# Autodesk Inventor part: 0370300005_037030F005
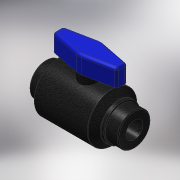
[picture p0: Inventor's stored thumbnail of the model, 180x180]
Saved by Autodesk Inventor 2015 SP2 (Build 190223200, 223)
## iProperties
Created: 2017-06
Part Number: 0370300005_037030F005
Material: PVC-Piping
Description: PLASSON BALL VALVE DN20 FEMALE 1/2" BSPT
Document SubType Name: Modeling
Designer: KIM
Mass: 260.823 g
Surface Area: 282.049 cm^2
Volume: 186.302 cm^3
Density: 1.4 g/cm^3
Appearance: Black Cast
Author: KIM
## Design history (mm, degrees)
derived "03703.ipt"
feature "Solid1::03703.ipt"
tag "TaggingFeature1"
body "Solid1"
other parameters: "d0" = 97, "d3" = 54, "d4" = 17, "d5" = 18.631, "d6" = 18.631, "d7" = 17, "d8" = 36, "d9" = 13.6, "d10" = 39.6, "d11" = 15.0485, "d12" = 135 deg, "d14" = 0.93155, "d24" = 11.1786, "d25" = 35.1, "d27" = 11.1786, "d28" = 5.5893, "d29" = 18.9, "d30" = 0, "d32" = 24.59292, "d33" = 2.79465, "d34" = 0.93155, "Rc_" = 18.631, "A_1" = 27, "A_2" = 54, "H_" = 97, "l_" = 17, "B_" = 36, "E_" = 1, "d31" = 22.3572
